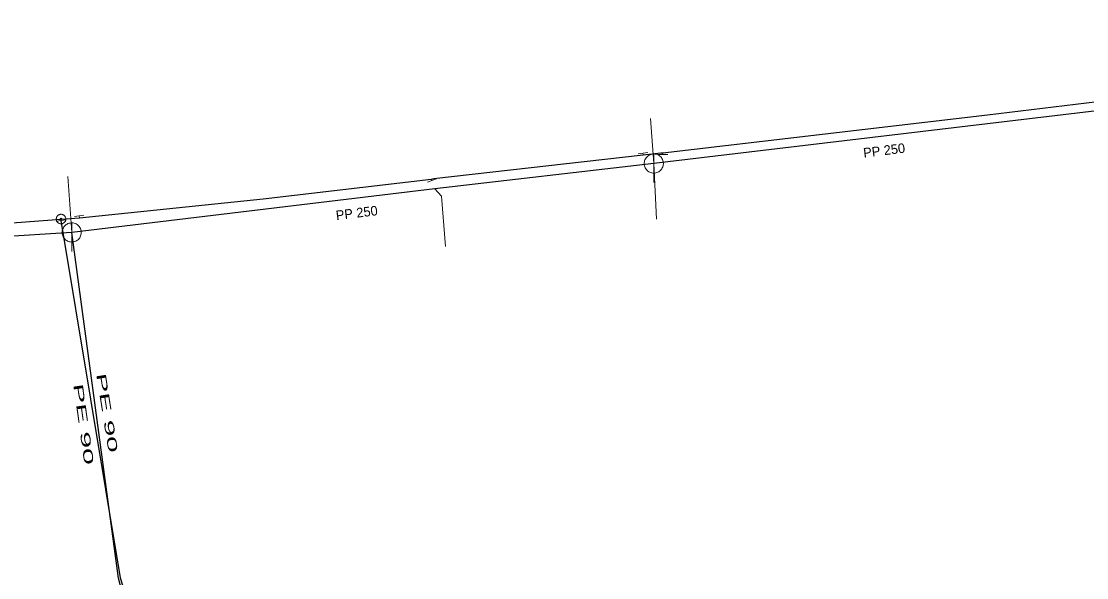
# Model space of a CAD drawing. Extents: x -659250 to -657316, y -997555 to -993684.
# Drawn here: x -658390.8 to -658279.6, y -994938 to -994879.9 of the extents above; entities that cross this region are included whole.
import ezdxf

# ---------------------------------------------------------------- set-up
doc = ezdxf.new("R2010")
doc.units = 0
doc.header["$LTSCALE"] = 0.4
doc.layers.add('1', color=7, linetype='Continuous')
for name, color, linetype, lineweight in [('11', 7, 'Continuous', 13), ('14', 7, 'Continuous', 25), ('17', 7, 'Continuous', 25), ('22', 7, 'Continuous', 13), ('34', 7, 'Continuous', 13), ('47', 7, 'Continuous', 13)]:
    doc.layers.add(name, color=color, linetype=linetype, lineweight=lineweight)

msp = doc.modelspace()

# ---------------------------------------------------------------- linework, layer by layer
at = {"layer": '11'}
for p, q in [((-658325.149, -994890), (-658324.8, -994894.71)), ((-658324.51, -994900.51), (-658324.8, -994894.71)), ((-658385.989, -994896.059), (-658385.579, -994901.91))]:
    msp.add_line(p, q, dxfattribs=at)
msp.add_lwpolyline([(-658346.56, -994903.379), (-658346.96, -994898.12), (-658347.68, -994897.34)], dxfattribs=at)
at = {"layer": '14'}
for p, q in [((-658275.439, -994888.85), (-658324.8, -994894.71)), ((-658385.579, -994901.91), (-658409.53, -994903.399))]:
    msp.add_line(p, q, dxfattribs=at)
at = {"layer": '14', "lineweight": 13}
for p, q in [((-658325.91, -994893.8), (-658325.93, -994893.629)), ((-658323.85, -994893.6), (-658323.85, -994893.77)), ((-658348.03, -994896.329), (-658347.969, -994896.489)), ((-658386.693, -994900.657), (-658386.706, -994900.515)), ((-658384.77, -994900.37), (-658384.8, -994900.17))]:
    msp.add_line(p, q, dxfattribs=at)
at = {"layer": '14'}
for points in [[(-658324.8, -994894.71), (-658347.68, -994897.34), (-658385.579, -994901.91)], [(-658374.55, -994965.079), (-658374.59, -994964.87), (-658374.59, -994963.989), (-658376.02, -994955.75), (-658376.559, -994953.82), (-658380.68, -994938.03), (-658385.579, -994901.91)]]:
    msp.add_lwpolyline(points, dxfattribs=at)
at = {"layer": '17'}
for points in [[(-658386.698, -994900.514), (-658384.77, -994900.37), (-658365.6, -994898.41), (-658348.03, -994896.329), (-658347.76, -994896.26), (-658329.91, -994894.239), (-658325.91, -994893.8), (-658324.05, -994893.6), (-658323.85, -994893.6), (-658289.96, -994889.62), (-658276.16, -994887.96), (-658274.73, -994887.69), (-658259.189, -994885.859), (-658235.76, -994883.17), (-658228.649, -994882.27), (-658225.819, -994881.93), (-658224.199, -994881.739), (-658222.71, -994881.559), (-658219.819, -994881.199), (-658214.989, -994881.03), (-658213.939, -994880.859), (-658212.899, -994880.57), (-658211.41, -994879.859)], [(-658456.829, -994908.12), (-658410.35, -994902.34), (-658408.609, -994902.16), (-658386.698, -994900.514)], [(-658363.318, -994963.144), (-658373.289, -994964.469), (-658373.59, -994964.48), (-658373.77, -994963.6), (-658375.399, -994955.379), (-658375.829, -994953.609), (-658380.5, -994937.969), (-658386.693, -994900.657)]]:
    msp.add_lwpolyline(points, dxfattribs=at)
at = {"layer": '22'}
for p, q in [((-658324.8, -994896.71), (-658324.799, -994893.71)), ((-658385.579, -994903.91), (-658385.578, -994900.91))]:
    msp.add_line(p, q, dxfattribs=at)
for points in [[(-658323.8, -994894.71), (-658323.805, -994894.601), (-658323.823, -994894.493), (-658323.853, -994894.387), (-658323.893, -994894.286), (-658323.945, -994894.189), (-658324.007, -994894.099), (-658324.079, -994894.016), (-658324.159, -994893.942), (-658324.247, -994893.876), (-658324.341, -994893.821), (-658324.441, -994893.776), (-658324.546, -994893.743), (-658324.653, -994893.721), (-658324.762, -994893.711), (-658324.872, -994893.713), (-658324.98, -994893.727), (-658325.087, -994893.752), (-658325.19, -994893.789), (-658325.288, -994893.838), (-658325.38, -994893.896), (-658325.466, -994893.965), (-658325.543, -994894.042), (-658325.612, -994894.128), (-658325.671, -994894.22), (-658325.719, -994894.318), (-658325.756, -994894.421), (-658325.782, -994894.528), (-658325.796, -994894.636), (-658325.799, -994894.746), (-658325.789, -994894.855), (-658325.768, -994894.962), (-658325.734, -994895.066), (-658325.69, -994895.166), (-658325.635, -994895.261), (-658325.569, -994895.349), (-658325.495, -994895.429), (-658325.412, -994895.501), (-658325.322, -994895.563), (-658325.226, -994895.615), (-658325.124, -994895.656), (-658325.019, -994895.686), (-658324.911, -994895.704), (-658324.801, -994895.71), (-658324.692, -994895.704), (-658324.584, -994895.686), (-658324.479, -994895.657), (-658324.377, -994895.616), (-658324.28, -994895.564), (-658324.19, -994895.502), (-658324.107, -994895.431), (-658324.032, -994895.351), (-658323.967, -994895.263), (-658323.911, -994895.169), (-658323.867, -994895.069), (-658323.833, -994894.965), (-658323.811, -994894.857), (-658323.801, -994894.748)], [(-658384.579, -994901.91), (-658384.584, -994901.801), (-658384.602, -994901.693), (-658384.632, -994901.587), (-658384.672, -994901.486), (-658384.724, -994901.389), (-658384.786, -994901.299), (-658384.858, -994901.216), (-658384.938, -994901.142), (-658385.026, -994901.076), (-658385.12, -994901.021), (-658385.22, -994900.976), (-658385.325, -994900.943), (-658385.432, -994900.921), (-658385.541, -994900.911), (-658385.651, -994900.913), (-658385.759, -994900.927), (-658385.866, -994900.952), (-658385.969, -994900.989), (-658386.067, -994901.038), (-658386.159, -994901.096), (-658386.245, -994901.165), (-658386.322, -994901.242), (-658386.391, -994901.328), (-658386.45, -994901.42), (-658386.498, -994901.518), (-658386.535, -994901.621), (-658386.561, -994901.728), (-658386.575, -994901.836), (-658386.578, -994901.946), (-658386.568, -994902.055), (-658386.547, -994902.162), (-658386.513, -994902.266), (-658386.469, -994902.366), (-658386.414, -994902.461), (-658386.348, -994902.549), (-658386.274, -994902.629), (-658386.191, -994902.701), (-658386.101, -994902.763), (-658386.005, -994902.815), (-658385.903, -994902.856), (-658385.798, -994902.886), (-658385.69, -994902.904), (-658385.58, -994902.91), (-658385.471, -994902.904), (-658385.363, -994902.886), (-658385.258, -994902.857), (-658385.156, -994902.816), (-658385.059, -994902.764), (-658384.969, -994902.702), (-658384.886, -994902.631), (-658384.811, -994902.551), (-658384.746, -994902.463), (-658384.69, -994902.369), (-658384.646, -994902.269), (-658384.612, -994902.165), (-658384.59, -994902.057), (-658384.58, -994901.948)]]:
    msp.add_lwpolyline(points, close=True, dxfattribs=at)
at = {"layer": '34'}
for p, q in [((-658326.426, -994893.687), (-658325.433, -994893.571)), ((-658323.35, -994893.769), (-658324.35, -994893.769)), ((-658347.501, -994896.312), (-658348.437, -994896.664)), ((-658385.294, -994900.244), (-658384.305, -994900.096)), ((-658387.186, -994900.739), (-658386.199, -994900.575))]:
    msp.add_line(p, q, dxfattribs=at)
at = {"layer": '47'}
for points in [[(-658386.198, -994900.514), (-658386.201, -994900.462), (-658386.209, -994900.409), (-658386.223, -994900.36), (-658386.24, -994900.311), (-658386.265, -994900.264), (-658386.294, -994900.22), (-658386.326, -994900.179), (-658386.364, -994900.142), (-658386.404, -994900.11), (-658386.448, -994900.081), (-658386.495, -994900.056), (-658386.544, -994900.039), (-658386.593, -994900.025), (-658386.646, -994900.017), (-658386.698, -994900.014), (-658386.75, -994900.017), (-658386.802, -994900.025), (-658386.853, -994900.039), (-658386.901, -994900.056), (-658386.948, -994900.081), (-658386.992, -994900.11), (-658387.032, -994900.142), (-658387.07, -994900.179), (-658387.103, -994900.22), (-658387.13, -994900.264), (-658387.155, -994900.311), (-658387.174, -994900.36), (-658387.186, -994900.409), (-658387.195, -994900.462), (-658387.198, -994900.514), (-658387.195, -994900.566), (-658387.186, -994900.618), (-658387.174, -994900.669), (-658387.155, -994900.717), (-658387.13, -994900.764), (-658387.103, -994900.808), (-658387.07, -994900.848), (-658387.032, -994900.886), (-658386.992, -994900.919), (-658386.948, -994900.946), (-658386.901, -994900.971), (-658386.853, -994900.99), (-658386.802, -994901.002), (-658386.75, -994901.011), (-658386.698, -994901.014), (-658386.646, -994901.011), (-658386.593, -994901.002), (-658386.544, -994900.99), (-658386.495, -994900.971), (-658386.448, -994900.946), (-658386.404, -994900.919), (-658386.364, -994900.886), (-658386.326, -994900.848), (-658386.294, -994900.808), (-658386.265, -994900.764), (-658386.24, -994900.717), (-658386.223, -994900.669), (-658386.209, -994900.618), (-658386.201, -994900.566)], [(-658386.615, -994900.514), (-658386.615, -994900.505), (-658386.618, -994900.497), (-658386.62, -994900.489), (-658386.623, -994900.48), (-658386.627, -994900.473), (-658386.632, -994900.466), (-658386.637, -994900.458), (-658386.642, -994900.453), (-658386.65, -994900.448), (-658386.657, -994900.443), (-658386.664, -994900.439), (-658386.673, -994900.436), (-658386.681, -994900.434), (-658386.689, -994900.431), (-658386.698, -994900.431), (-658386.706, -994900.431), (-658386.715, -994900.434), (-658386.723, -994900.436), (-658386.731, -994900.439), (-658386.739, -994900.443), (-658386.745, -994900.448), (-658386.753, -994900.453), (-658386.759, -994900.458), (-658386.765, -994900.466), (-658386.769, -994900.473), (-658386.772, -994900.48), (-658386.776, -994900.489), (-658386.777, -994900.497), (-658386.78, -994900.505), (-658386.78, -994900.514), (-658386.78, -994900.522), (-658386.777, -994900.531), (-658386.776, -994900.539), (-658386.772, -994900.547), (-658386.769, -994900.554), (-658386.765, -994900.561), (-658386.759, -994900.569), (-658386.753, -994900.575), (-658386.745, -994900.581), (-658386.739, -994900.585), (-658386.731, -994900.588), (-658386.723, -994900.592), (-658386.715, -994900.593), (-658386.706, -994900.596), (-658386.698, -994900.596), (-658386.689, -994900.596), (-658386.681, -994900.593), (-658386.673, -994900.592), (-658386.664, -994900.588), (-658386.657, -994900.585), (-658386.65, -994900.581), (-658386.642, -994900.575), (-658386.637, -994900.569), (-658386.632, -994900.561), (-658386.627, -994900.554), (-658386.623, -994900.547), (-658386.62, -994900.539), (-658386.618, -994900.531), (-658386.615, -994900.522)]]:
    msp.add_lwpolyline(points, close=True, dxfattribs=at)

# ---------------------------------------------------------------- texts
at = {"layer": '1'}
for p in [(-658302.864, -994894.104), (-658357.935, -994900.634)]:
    msp.add_text('PP 250', height=1, rotation=7, dxfattribs=at).set_placement(p)
for rotation, width, p in [(279, 2.3, (-658383.033, -994916.685)), (278, 2.35, (-658385.432, -994917.758))]:
    msp.add_text('PE 90 ', height=1, rotation=rotation, dxfattribs=dict(at, width=width)).set_placement(p)

doc.saveas('drawing.dxf')
